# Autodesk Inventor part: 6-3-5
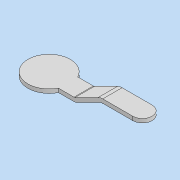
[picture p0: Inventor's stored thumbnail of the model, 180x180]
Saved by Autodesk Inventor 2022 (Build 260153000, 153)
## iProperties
Created: 2021-07
Part Number: 6-3-5
Material: 一般
Document SubType Name: Modeling
Designer: DesignLab
Density: 1 g/cm^3
Appearance: 既定
Author: DesignLab
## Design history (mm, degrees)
sketch "スケッチ1"
  geometry: L1 (25, 0)-(-28, 0); L2 (-28, 0)-(-48, 10); L3 (-48, 10)-(-100, 10); 1 further point
  constraints: 6 end point, 1 horizontal, 1 parallel, 1 point on line
  dimensions: "d0" = 25 distance of point (0, 0) L1.start; "d1" = 100 horizontal distance of L3.end point (0, 0); "d2" = 10 distance between parallel lines of L1 L3; "d3" = 28 distance of L1.end point (0, 0); "d4" = 20 horizontal distance of L1.end L2.end
feature "押し出しサーフェス1" sketch "スケッチ1" dims "d5" = 40, "d6" = 0
fillet "フィレット1" dims "d7" = 5
feature "厚み1" dims "d8" = 3
sketch "スケッチ2"
  geometry: L1 (-49.18, 20)-(30.82, 20); L2 (-41.68, 12.5)-(23.32, 12.5); L3 (23.32, 27.5)-(-41.68, 27.5); C1 r 16.5 at (-49.18, 20); A1 r 7.5 centre (-41.68, 20) between (-41.68, 27.5) and (-41.68, 12.5); A2 r 7.5 centre (23.32, 20) between (23.32, 12.5) and (23.32, 27.5); 4 further points
  constraints: 8 end point, 6 point on circle, 4 tangent, 3 centre point, 2 point on line, 1 coincident, 1 horizontal, 1 midpoint, 1 parallel
  dimensions: "d9" = 33 diameter of C1; "d10" = 80 distance of L1.start L1.end; "d11" = 15 diameter of A2
extrude "押し出し1" sketch "スケッチ2" extent not by distance; stored distance "d12" = 0; taper "d13" = 0 deg
node "ソリッド1"
body "Srf1"
